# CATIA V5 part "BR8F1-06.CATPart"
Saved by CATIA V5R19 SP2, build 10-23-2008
Part number: BR8F1-06
Definition: design
Nomenclature: BR8F1-06
Source: Unknown
Bounding box of the stored display mesh (mm): x -3.9 to 11.15, y 0 to 18.1, z 0 to 30.48
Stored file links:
  Z:\fausse table rondelle-20220905T211342Z-001\fausse table rondelle\BR8F1-06.CATPart
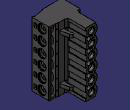
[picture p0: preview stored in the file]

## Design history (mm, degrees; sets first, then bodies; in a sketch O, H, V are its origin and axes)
AxisSystem1: origin (0, 0, 0), X (1, 0, 0), Y (0, 1, 0), Z (0, 0, 1)
Body1 "MANIFOLD_SOLID_BREP #102016" (main body)
  Solid1: solid without history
